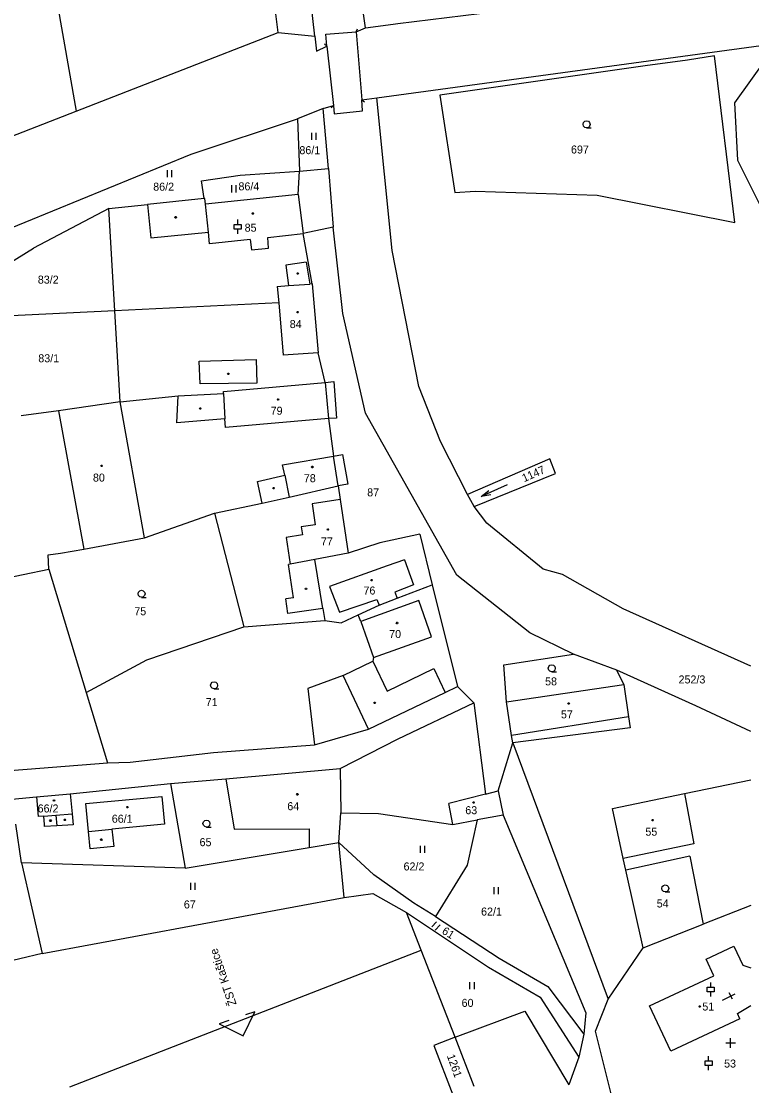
# Model space of a CAD drawing. Extents: x -812394 to -807601, y -1013097 to -1009266.
# Drawn here: x -809780.5 to -809625.5, y -1011039 to -1010813 of the extents above; entities that cross this region are included whole.
import ezdxf

# ---------------------------------------------------------------- set-up
doc = ezdxf.new("R2010")
doc.units = 0
for name, color, linetype in [('Default', 7, 'Continuous'), ('KN_HRANICE', 7, 'Continuous'), ('KN_KULTURY', 7, 'Continuous'), ('KN_PARCELY', 7, 'Continuous'), ('KN_SLUCKY', 7, 'Continuous')]:
    doc.layers.add(name, color=color, linetype=linetype)

# ---------------------------------------------------------------- blocks, each defined once
blk = doc.blocks.new('4201')
at = {"layer": 'Default'}
blk.add_line((0, 0), (-0.5, -0.5), dxfattribs=at)
blk = doc.blocks.new('304')
at = {"layer": 'Default'}
blk.add_lwpolyline([(0, 0), (-0.38, 0.1), (-0.65, 0.37), (-0.75, 0.74), (-0.65, 1.11), (-0.38, 1.38), (-0.01, 1.48), (0.36, 1.38), (0.63, 1.11), (0.73, 0.73), (0.63, 0.35), (0.36, 0.08), (-0.02, -0.02), (0.98, -0.02)], dxfattribs=at)
blk = doc.blocks.new('306')
at = {"layer": 'Default'}
for p, q in [((-0.5, 1.5), (-0.5, 0)), ((0.5, 0), (0.5, 1.5))]:
    blk.add_line(p, q, dxfattribs=at)
blk = doc.blocks.new('315')
at = {"layer": 'Default'}
for p, q in [((-1, 1), (1, 1)), ((0, 0), (0, 2))]:
    blk.add_line(p, q, dxfattribs=at)
blk = doc.blocks.new('NAHRADNI_SYMBOL')
at = {"layer": 'Default'}
blk.add_lwpolyline([(0.09, 0.15), (0.18, 0), (0.09, -0.15), (-0.09, -0.15), (-0.18, 0), (-0.09, 0.15), (0.09, 0.15)], dxfattribs=at)
blk = doc.blocks.new('802')
at = {"layer": 'Default'}
blk.add_line((-3, 0), (3, 0), dxfattribs=at)
blk.add_lwpolyline([(1, 0.5), (3, 0), (1, -0.5)], dxfattribs=at)
blk = doc.blocks.new('318')
at = {"layer": 'Default'}
blk.add_line((0, 2), (0, 3), dxfattribs=at)
blk.add_lwpolyline([(0, 0), (0, 1), (-0.75, 1), (-0.75, 2), (0, 2), (0.75, 2), (0.75, 1), (0, 1)], dxfattribs=at)
blk = doc.blocks.new('402')
at = {"layer": 'Default'}
blk.add_lwpolyline([(0.09, 0.15), (0.18, 0), (0.09, -0.15), (-0.09, -0.15), (-0.18, 0), (-0.09, 0.15), (0.09, 0.15)], dxfattribs=at)
blk = doc.blocks.new('4091')
at = {"layer": 'Default'}
for p, q in [((0, 0), (0, 3)), ((0.75, 2), (-0.75, 2))]:
    blk.add_line(p, q, dxfattribs=at)

msp = doc.modelspace()

# ---------------------------------------------------------------- linework, layer by layer
at = {"layer": 'Default'}
msp.add_lwpolyline([(-809736.51, -1011025.2), (-809738.53, -1011025.87), (-809733.47, -1011028.41), (-809730.93, -1011023.35), (-809732.95, -1011024.02)], dxfattribs=at)
at = {"layer": 'KN_HRANICE'}
for p, q in [((-809776.12, -1010790.59), (-809768.91, -1010832.11)), ((-809718.25, -1010816.21), (-809720.85, -1010791.69)), ((-809707.49, -1010814.44), (-809710.32, -1010793.53)), ((-809726.02, -1010815.44), (-809727.35, -1010804.19)), ((-809700.6, -1010813.52), (-809643.49, -1010806.47)), ((-809709.48, -1010815.3), (-809707.49, -1010814.44)), ((-809707.49, -1010814.44), (-809701.59, -1010813.65)), ((-809701.59, -1010813.65), (-809700.6, -1010813.52)), ((-809768.91, -1010832.11), (-809726.02, -1010815.44)), ((-809726.02, -1010815.44), (-809718.25, -1010816.21)), ((-809718.25, -1010816.21), (-809717.84, -1010819.37)), ((-809715.88, -1010815.78), (-809709.48, -1010815.3)), ((-809715.65, -1010818.36), (-809715.88, -1010815.78)), ((-809705.08, -1010829.3), (-809609.07, -1010816.23)), ((-809717.84, -1010819.37), (-809715.65, -1010818.36)), ((-809622.36, -1010820.88), (-809629.15, -1010830.35)), ((-809708.23, -1010829.73), (-809705.08, -1010829.3)), ((-809708.1, -1010832.05), (-809708.23, -1010829.73)), ((-809701.84, -1010861.69), (-809705.08, -1010829.3)), ((-809629.15, -1010830.35), (-809628.52, -1010842.52)), ((-809795, -1010842.25), (-809768.91, -1010832.11)), ((-809716.45, -1010831.55), (-809721.87, -1010833.74)), ((-809716.45, -1010831.55), (-809714.29, -1010830.95)), ((-809715.34, -1010844.3), (-809716.45, -1010831.55)), ((-809714.29, -1010830.95), (-809714.1, -1010832.7)), ((-809714.1, -1010832.7), (-809708.1, -1010832.05)), ((-809744.44, -1010841.28), (-809721.87, -1010833.74)), ((-809721.87, -1010833.74), (-809721.48, -1010844.89)), ((-809788.59, -1010859.35), (-809744.44, -1010841.28)), ((-809628.52, -1010842.52), (-809623.05, -1010853.45)), ((-809742.28, -1010846.91), (-809734.04, -1010845.7)), ((-809734.04, -1010845.7), (-809721.48, -1010844.89)), ((-809721.76, -1010849.8), (-809721.48, -1010844.89)), ((-809721.48, -1010844.89), (-809715.34, -1010844.3)), ((-809715.34, -1010844.3), (-809714.35, -1010856.77)), ((-809741.74, -1010850.68), (-809742.28, -1010846.91)), ((-809741.74, -1010850.68), (-809753.76, -1010851.95)), ((-809741.55, -1010850.66), (-809741.74, -1010850.68)), ((-809741.42, -1010851.87), (-809741.55, -1010850.66)), ((-809721.76, -1010849.8), (-809741.42, -1010851.87)), ((-809761.95, -1010852.82), (-809777.96, -1010861.22)), ((-809761.95, -1010852.82), (-809753.76, -1010851.95)), ((-809760.65, -1010874.53), (-809761.95, -1010852.82)), ((-809714.35, -1010856.77), (-809720.67, -1010858.1)), ((-809712.26, -1010875.07), (-809714.35, -1010856.77)), ((-809718.78, -1010868.81), (-809720.67, -1010858.1)), ((-809791.19, -1010869.46), (-809777.96, -1010861.22)), ((-809696.17, -1010890.56), (-809701.84, -1010861.69)), ((-809723.78, -1010869.17), (-809719.27, -1010868.85)), ((-809718.78, -1010868.81), (-809719.27, -1010868.85)), ((-809718.78, -1010868.81), (-809717.54, -1010883.42)), ((-809726.19, -1010869.35), (-809723.78, -1010869.17)), ((-809726.19, -1010869.35), (-809725.89, -1010872.83)), ((-809725.89, -1010872.83), (-809760.65, -1010874.53)), ((-809760.65, -1010874.53), (-809789.4, -1010875.94)), ((-809759.51, -1010893.83), (-809760.65, -1010874.53)), ((-809707.45, -1010896.24), (-809712.26, -1010875.07)), ((-809716.06, -1010889.76), (-809717.54, -1010883.42)), ((-809737.62, -1010891.67), (-809716.06, -1010889.76)), ((-809737.6, -1010892.07), (-809737.62, -1010891.67)), ((-809716.06, -1010889.76), (-809714.21, -1010889.51)), ((-809714.21, -1010889.51), (-809713.65, -1010897.28)), ((-809691.58, -1010902.27), (-809696.17, -1010890.56)), ((-809759.51, -1010893.83), (-809772.62, -1010895.72)), ((-809759.51, -1010893.83), (-809747.26, -1010892.56)), ((-809754.39, -1010922.74), (-809759.51, -1010893.83)), ((-809747.26, -1010892.56), (-809737.6, -1010892.07)), ((-809772.62, -1010895.72), (-809780.58, -1010896.79)), ((-809772.62, -1010895.72), (-809767.28, -1010925.14)), ((-809713.65, -1010897.28), (-809715.33, -1010897.38)), ((-809715.33, -1010897.38), (-809714.24, -1010905.37)), ((-809688.11, -1010930.67), (-809707.45, -1010896.24)), ((-809685.82, -1010913.52), (-809691.58, -1010902.27)), ((-809714.24, -1010905.37), (-809712.36, -1010905.04)), ((-809712.36, -1010905.04), (-809711.25, -1010911.34)), ((-809725.07, -1010907.24), (-809714.24, -1010905.37)), ((-809724.57, -1010909.43), (-809725.07, -1010907.24)), ((-809730.42, -1010910.76), (-809724.57, -1010909.43)), ((-809729.38, -1010915.34), (-809730.42, -1010910.76)), ((-809723.69, -1010914.05), (-809713.3, -1010911.69)), ((-809711.25, -1010911.34), (-809713.3, -1010911.69)), ((-809713.3, -1010911.69), (-809712.87, -1010914.61)), ((-809729.38, -1010915.34), (-809723.69, -1010914.05)), ((-809684.42, -1010916.06), (-809685.82, -1010913.52)), ((-809739.53, -1010917.47), (-809729.38, -1010915.34)), ((-809712.87, -1010914.61), (-809711.14, -1010925.98)), ((-809681.71, -1010919.57), (-809684.42, -1010916.06)), ((-809754.39, -1010922.74), (-809739.53, -1010917.47)), ((-809739.53, -1010917.47), (-809733.26, -1010941.62)), ((-809669.73, -1010929.35), (-809681.71, -1010919.57)), ((-809767.28, -1010925.14), (-809754.39, -1010922.74)), ((-809695.97, -1010921.93), (-809704.43, -1010923.75)), ((-809695.97, -1010921.93), (-809693.3, -1010932.7)), ((-809772.22, -1010925.97), (-809767.28, -1010925.14)), ((-809704.43, -1010923.75), (-809711.14, -1010925.98)), ((-809774.81, -1010926.31), (-809772.22, -1010925.97)), ((-809774.68, -1010929.4), (-809774.81, -1010926.31)), ((-809711.14, -1010925.98), (-809718.2, -1010927.32)), ((-809716.52, -1010937.73), (-809718.2, -1010927.32)), ((-809810.23, -1010936.6), (-809774.68, -1010929.4)), ((-809774.68, -1010929.4), (-809766.75, -1010955.54)), ((-809665.64, -1010930.47), (-809669.73, -1010929.35)), ((-809672.58, -1010942.91), (-809688.11, -1010930.67)), ((-809652.76, -1010937.76), (-809665.64, -1010930.47)), ((-809700.73, -1010935.54), (-809693.3, -1010932.7)), ((-809693.3, -1010932.7), (-809687.95, -1010954.31)), ((-809704.57, -1010937), (-809700.73, -1010935.54)), ((-809716.52, -1010937.73), (-809716.12, -1010940.23)), ((-809712.62, -1010940.73), (-809708.99, -1010939.05)), ((-809708.99, -1010939.05), (-809704.57, -1010937)), ((-809708.43, -1010940.5), (-809708.99, -1010939.05)), ((-809625.71, -1010949.98), (-809652.76, -1010937.76)), ((-809733.26, -1010941.62), (-809716.12, -1010940.23)), ((-809716.12, -1010940.23), (-809712.62, -1010940.73)), ((-809708.43, -1010940.5), (-809705.79, -1010948.11)), ((-809753.89, -1010948.61), (-809733.26, -1010941.62)), ((-809663.31, -1010947.39), (-809672.58, -1010942.91)), ((-809705.79, -1010948.11), (-809705.9, -1010948.93)), ((-809678.08, -1010949.7), (-809663.31, -1010947.39)), ((-809654.15, -1010950.78), (-809663.31, -1010947.39)), ((-809766.75, -1010955.54), (-809753.89, -1010948.61)), ((-809712.21, -1010951.96), (-809705.9, -1010948.93)), ((-809677.51, -1010957.55), (-809678.08, -1010949.7)), ((-809712.21, -1010951.96), (-809719.69, -1010954.69)), ((-809637.34, -1010958.4), (-809654.15, -1010950.78)), ((-809652.62, -1010953.83), (-809654.15, -1010950.78)), ((-809719.69, -1010954.69), (-809718.32, -1010966.65)), ((-809690.53, -1010955.54), (-809687.95, -1010954.31)), ((-809687.95, -1010954.31), (-809684.45, -1010957.75)), ((-809677.51, -1010957.55), (-809652.62, -1010953.83)), ((-809652.62, -1010953.83), (-809651.63, -1010960.74)), ((-809766.75, -1010955.54), (-809762.22, -1010970.5)), ((-809706.83, -1010963.33), (-809690.53, -1010955.54)), ((-809700.5, -1010965.4), (-809684.45, -1010957.75)), ((-809684.45, -1010957.75), (-809682.01, -1010977.11)), ((-809676.47, -1010964.65), (-809677.51, -1010957.55)), ((-809625.71, -1010963.85), (-809637.34, -1010958.4)), ((-809651.63, -1010960.74), (-809651.3, -1010963.06)), ((-809718.32, -1010966.65), (-809706.83, -1010963.33)), ((-809651.3, -1010963.06), (-809676.23, -1010966.23)), ((-809712.82, -1010971.72), (-809700.5, -1010965.4)), ((-809679.34, -1010976.42), (-809676.23, -1010966.23)), ((-809676.23, -1010966.23), (-809676.47, -1010964.65)), ((-809676.23, -1010966.23), (-809655.96, -1011020.63)), ((-809757.42, -1010970.37), (-809739.76, -1010968.28)), ((-809739.76, -1010968.28), (-809718.32, -1010966.65)), ((-809785.75, -1010972.3), (-809762.22, -1010970.5)), ((-809762.22, -1010970.5), (-809757.42, -1010970.37)), ((-809737.1, -1010973.85), (-809712.82, -1010971.72)), ((-809712.82, -1010971.72), (-809712.69, -1010981.07)), ((-809770.14, -1010977.1), (-809748.85, -1010974.88)), ((-809748.85, -1010974.88), (-809737.1, -1010973.85)), ((-809748.85, -1010974.88), (-809745.78, -1010992.82)), ((-809737.1, -1010973.85), (-809735.37, -1010984.59)), ((-809639.78, -1010977.02), (-809625.71, -1010974.08)), ((-809777.31, -1010977.72), (-809770.14, -1010977.1)), ((-809770.14, -1010977.1), (-809769.76, -1010981.28)), ((-809682.01, -1010977.11), (-809679.34, -1010976.42)), ((-809679.34, -1010976.42), (-809678.26, -1010981.58)), ((-809655.06, -1010980.16), (-809639.78, -1010977.02)), ((-809782.57, -1010978.23), (-809777.31, -1010977.72)), ((-809777.31, -1010977.72), (-809776.92, -1010981.88)), ((-809775.78, -1010981.78), (-809776.92, -1010981.88)), ((-809775.61, -1010983.58), (-809775.78, -1010981.78)), ((-809769.76, -1010981.28), (-809769.54, -1010983.67)), ((-809713.13, -1010987.41), (-809712.69, -1010981.07)), ((-809712.69, -1010981.07), (-809704.69, -1010981.22)), ((-809704.69, -1010981.22), (-809688.94, -1010983.58)), ((-809678.26, -1010981.58), (-809683.77, -1010982.61)), ((-809678.26, -1010981.58), (-809660.72, -1011023.58)), ((-809652.76, -1010990.81), (-809655.06, -1010980.16)), ((-809780.48, -1010991.7), (-809781.71, -1010983.51)), ((-809775.59, -1010983.98), (-809775.61, -1010983.58)), ((-809772.99, -1010983.85), (-809775.59, -1010983.98)), ((-809769.54, -1010983.67), (-809772.99, -1010983.85)), ((-809688.94, -1010983.58), (-809683.77, -1010982.61)), ((-809683.77, -1010982.61), (-809685.91, -1010992.23)), ((-809735.37, -1010984.59), (-809719.45, -1010984.53)), ((-809719.45, -1010984.53), (-809719.41, -1010988.45)), ((-809745.78, -1010992.82), (-809719.41, -1010988.45)), ((-809719.41, -1010988.45), (-809713.13, -1010987.41)), ((-809712.03, -1010999.08), (-809713.13, -1010987.41)), ((-809705.68, -1010994.29), (-809713.13, -1010987.41)), ((-809652.21, -1010993.26), (-809652.76, -1010990.81)), ((-809638.59, -1010990.28), (-809652.21, -1010993.26)), ((-809638.59, -1010990.28), (-809635.78, -1011004.74)), ((-809780.48, -1010991.7), (-809776.12, -1011010.98)), ((-809745.78, -1010992.82), (-809780.48, -1010991.7)), ((-809685.91, -1010992.23), (-809692.6, -1011003.11)), ((-809648.52, -1011009.77), (-809652.21, -1010993.26)), ((-809697.2, -1011000.25), (-809705.68, -1010994.29)), ((-809776.12, -1011010.98), (-809712.03, -1010999.08)), ((-809712.03, -1010999.08), (-809705.9, -1010998.23)), ((-809705.9, -1010998.23), (-809698.74, -1011002.28)), ((-809695.65, -1011010.24), (-809698.74, -1011002.28)), ((-809698.74, -1011002.28), (-809681.36, -1011013.87)), ((-809692.6, -1011003.11), (-809697.2, -1011000.25)), ((-809625.71, -1011000.77), (-809635.78, -1011004.74)), ((-809692.6, -1011003.11), (-809679.1, -1011011.97)), ((-809648.52, -1011009.77), (-809635.78, -1011004.74)), ((-809776.12, -1011010.98), (-809797.21, -1011015.92)), ((-809770.25, -1011039.27), (-809695.65, -1011010.24)), ((-809688.47, -1011028.73), (-809695.65, -1011010.24)), ((-809655.96, -1011020.63), (-809648.52, -1011009.77)), ((-809635.16, -1011012.17), (-809629.28, -1011009.42)), ((-809629.28, -1011009.42), (-809627.41, -1011013.42)), ((-809679.1, -1011011.97), (-809668.78, -1011017.98)), ((-809633.51, -1011015.71), (-809635.16, -1011012.17)), ((-809627.41, -1011013.42), (-809625.71, -1011014)), ((-809681.36, -1011013.87), (-809670.36, -1011020.23)), ((-809647.18, -1011022.1), (-809633.51, -1011015.71)), ((-809668.78, -1011017.98), (-809661.16, -1011028.1)), ((-809670.36, -1011020.23), (-809662.17, -1011032.99)), ((-809658.63, -1011027.44), (-809655.96, -1011020.63)), ((-809642.69, -1011031.69), (-809647.18, -1011022.1)), ((-809628.49, -1011023.72), (-809625.71, -1011022)), ((-809688.47, -1011028.73), (-809673.64, -1011023.19)), ((-809673.64, -1011023.19), (-809664.28, -1011038.85)), ((-809660.72, -1011023.58), (-809661.16, -1011028.1)), ((-809627.98, -1011024.81), (-809642.69, -1011031.69)), ((-809627.98, -1011024.81), (-809628.49, -1011023.72)), ((-809688.47, -1011028.73), (-809692.99, -1011030.49)), ((-809684.4, -1011039.22), (-809688.47, -1011028.73)), ((-809661.16, -1011028.1), (-809662.17, -1011032.99)), ((-809652.22, -1011053.19), (-809658.63, -1011027.44)), ((-809692.99, -1011030.49), (-809688.92, -1011040.98)), ((-809662.17, -1011032.99), (-809664.28, -1011038.85))]:
    msp.add_line(p, q, dxfattribs=at)
msp.add_lwpolyline([(-809691.7, -1010828.74), (-809688.53, -1010849.4), (-809684.21, -1010849.11), (-809658.29, -1010849.93), (-809629.1, -1010855.77), (-809633.37, -1010820.41), (-809639.13, -1010821.28), (-809648.14, -1010822.51)], close=True, dxfattribs=at)
msp.add_lwpolyline([(-809684.42, -1010916.06), (-809667.12, -1010909.09), (-809668.31, -1010905.92), (-809685.82, -1010913.52)], dxfattribs=at)
at = {"layer": 'KN_SLUCKY'}
for p, q in [((-809709.48, -1010815.3), (-809708.23, -1010829.73)), ((-809715.65, -1010818.36), (-809714.29, -1010830.95)), ((-809721.76, -1010849.8), (-809720.67, -1010858.1)), ((-809753.76, -1010851.95), (-809753.04, -1010859)), ((-809740.79, -1010857.85), (-809741.42, -1010851.87)), ((-809753.04, -1010859), (-809740.79, -1010857.85)), ((-809740.55, -1010860.29), (-809740.79, -1010857.85)), ((-809731.95, -1010859.34), (-809740.55, -1010860.29)), ((-809731.95, -1010859.34), (-809731.7, -1010861.58)), ((-809728.23, -1010858.97), (-809720.67, -1010858.1)), ((-809728.04, -1010861.21), (-809728.23, -1010858.97)), ((-809731.7, -1010861.58), (-809728.04, -1010861.21)), ((-809720.09, -1010864.16), (-809724.37, -1010864.8)), ((-809720.09, -1010864.16), (-809719.27, -1010868.85)), ((-809724.37, -1010864.8), (-809723.78, -1010869.17)), ((-809725.89, -1010872.83), (-809724.95, -1010883.96)), ((-809742.8, -1010885.24), (-809730.68, -1010884.82)), ((-809730.68, -1010884.82), (-809730.54, -1010889.91)), ((-809717.54, -1010883.42), (-809724.95, -1010883.96)), ((-809742.56, -1010890.05), (-809742.8, -1010885.24)), ((-809730.54, -1010889.91), (-809742.56, -1010890.05)), ((-809716.06, -1010889.76), (-809715.33, -1010897.38)), ((-809747.53, -1010898.29), (-809747.26, -1010892.56)), ((-809737.6, -1010892.07), (-809737.3, -1010897.44)), ((-809737.3, -1010897.44), (-809747.53, -1010898.29)), ((-809737.2, -1010899.28), (-809737.3, -1010897.44)), ((-809715.33, -1010897.38), (-809737.2, -1010899.28)), ((-809713.3, -1010911.69), (-809714.24, -1010905.37)), ((-809724.57, -1010909.43), (-809723.69, -1010914.05)), ((-809712.87, -1010914.61), (-809718.8, -1010915.51)), ((-809718.8, -1010915.51), (-809718.12, -1010919.96)), ((-809718.12, -1010919.96), (-809721.09, -1010920.41)), ((-809721.09, -1010920.41), (-809720.83, -1010922.09)), ((-809720.83, -1010922.09), (-809724.3, -1010922.62)), ((-809724.3, -1010922.62), (-809723.43, -1010928.32)), ((-809718.2, -1010927.32), (-809723.43, -1010928.32)), ((-809699.21, -1010927.36), (-809702.88, -1010928.67)), ((-809699.21, -1010927.36), (-809697.31, -1010932.7)), ((-809723.43, -1010928.32), (-809723.82, -1010928.4)), ((-809722.74, -1010935.45), (-809723.82, -1010928.4)), ((-809702.88, -1010928.67), (-809715.13, -1010933.03)), ((-809715.13, -1010933.03), (-809713, -1010938.48)), ((-809697.31, -1010932.7), (-809701.21, -1010934.27)), ((-809701.21, -1010934.27), (-809700.73, -1010935.54)), ((-809722.74, -1010935.45), (-809724.36, -1010935.68)), ((-809723.94, -1010938.79), (-809724.36, -1010935.68)), ((-809713, -1010938.48), (-809705.03, -1010935.8)), ((-809696.16, -1010936.04), (-809708.43, -1010940.5)), ((-809705.03, -1010935.8), (-809704.57, -1010937)), ((-809693.48, -1010943.7), (-809696.16, -1010936.04)), ((-809716.52, -1010937.73), (-809723.94, -1010938.79)), ((-809705.79, -1010948.11), (-809693.48, -1010943.7)), ((-809705.9, -1010948.93), (-809702.87, -1010955.24)), ((-809706.83, -1010963.33), (-809712.21, -1010951.96)), ((-809702.87, -1010955.24), (-809692.96, -1010950.48)), ((-809692.96, -1010950.48), (-809690.53, -1010955.54)), ((-809651.63, -1010960.74), (-809676.47, -1010964.65)), ((-809682.01, -1010977.11), (-809689.78, -1010979.12)), ((-809639.78, -1010977.02), (-809637.75, -1010987.67)), ((-809766.85, -1010979.12), (-809750.67, -1010977.62)), ((-809766.28, -1010985.05), (-809766.85, -1010979.12)), ((-809750.67, -1010977.62), (-809750.11, -1010983.48)), ((-809688.94, -1010983.58), (-809689.78, -1010979.12)), ((-809775.78, -1010981.78), (-809773.19, -1010981.57)), ((-809773.19, -1010981.57), (-809769.76, -1010981.28)), ((-809773.19, -1010981.57), (-809772.99, -1010983.85)), ((-809750.11, -1010983.48), (-809761.28, -1010984.55)), ((-809766.28, -1010985.05), (-809761.28, -1010984.55)), ((-809765.93, -1010988.73), (-809766.28, -1010985.05)), ((-809761.28, -1010984.55), (-809760.92, -1010988.26)), ((-809760.92, -1010988.26), (-809765.93, -1010988.73)), ((-809637.75, -1010987.67), (-809652.76, -1010990.81))]:
    msp.add_line(p, q, dxfattribs=at)

# ---------------------------------------------------------------- block references
at = {"layer": 'KN_KULTURY'}
for name, p in [('304', (-809660.52, -1010835.66)), ('306', (-809718.42, -1010838.2)), ('306', (-809749.07, -1010846.12)), ('306', (-809735.43, -1010849.36)), ('402', (-809747.77, -1010854.66)), ('318', (-809734.6, -1010858.16)), ('402', (-809731.38, -1010853.87)), ('402', (-809721.84, -1010866.6)), ('402', (-809721.89, -1010874.78)), ('402', (-809736.58, -1010887.9)), ('402', (-809726.02, -1010893.37)), ('402', (-809742.55, -1010895.24)), ('402', (-809763.5, -1010907.41)), ('402', (-809718.74, -1010907.68)), ('402', (-809726.99, -1010912.19)), ('402', (-809715.45, -1010920.92)), ('402', (-809706.19, -1010931.69)), ('304', (-809754.99, -1010935.33)), ('402', (-809720.08, -1010933.54)), ('402', (-809700.76, -1010940.79)), ('304', (-809667.93, -1010951.15)), ('304', (-809739.6, -1010954.76)), ('402', (-809705.51, -1010957.74)), ('402', (-809664.34, -1010957.87)), ('NAHRADNI_SYMBOL', (-809721.91, -1010977.18)), ('402', (-809773.58, -1010978.48)), ('402', (-809757.99, -1010979.91)), ('402', (-809684.53, -1010978.92)), ('402', (-809774.33, -1010982.77)), ('402', (-809771.29, -1010982.58)), ('304', (-809741.22, -1010984.12)), ('402', (-809646.54, -1010982.66)), ('402', (-809763.57, -1010986.79)), ('306', (-809695.36, -1010989.6)), ('306', (-809744.14, -1010997.47)), ('306', (-809679.74, -1010998.4)), ('304', (-809643.82, -1010997.88)), ('306', (-809684.86, -1011018.57)), ('318', (-809634.18, -1011020.12)), ('402', (-809636.51, -1011022.21)), ('315', (-809629.96, -1011030.96)), ('318', (-809634.65, -1011035.76))]:
    msp.add_blockref(name, p, dxfattribs=at)
for name, p, rotation in [('802', (-809680.16, -1010912.72), -155.74054600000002), ('306', (-809693.02, -1011005.67), -42.294903), ('4091', (-809631.72, -1011020.9), -63.43704500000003)]:
    msp.add_blockref(name, p, dxfattribs=dict(at, rotation=rotation))
at = {"layer": 'KN_SLUCKY'}
for p, rotation in [((-809709.48, -1010815.3), -162.55874399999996), ((-809715.65, -1010818.36), -88.016935), ((-809708.23, -1010829.73), 99.465473)]:
    msp.add_blockref('4201', p, dxfattribs=dict(at, rotation=rotation))
msp.add_blockref('4201', (-809714.29, -1010830.95), dxfattribs=at)

# ---------------------------------------------------------------- texts
at = {"layer": 'Default'}
msp.add_text('ŽST Kaštice', height=1.75, rotation=109.0342, dxfattribs=at).set_placement((-809734.8, -1011021.75))
at = {"layer": 'KN_PARCELY'}
for s, p in [('86/1', (-809721.5, -1010841.26)), ('697', (-809663.85, -1010841.12)), ('86/2', (-809752.53, -1010849.01)), ('86/4', (-809734.43, -1010848.94)), ('85', (-809733.12, -1010857.71)), ('83/2', (-809777.02, -1010868.74)), ('84', (-809723.55, -1010878.18)), ('83/1', (-809776.92, -1010885.44)), ('79', (-809727.6, -1010896.58)), ('80', (-809765.32, -1010910.77)), ('78', (-809720.56, -1010910.9)), ('87', (-809707.11, -1010913.91)), ('77', (-809716.93, -1010924.34)), ('76', (-809707.9, -1010934.75)), ('75', (-809756.54, -1010939.15)), ('70', (-809702.45, -1010943.99)), ('58', (-809669.35, -1010954.04)), ('252/3', (-809641.02, -1010953.63)), ('71', (-809741.38, -1010958.44)), ('57', (-809665.98, -1010961.04)), ('66/2', (-809777.06, -1010981.02)), ('64', (-809724.07, -1010980.54)), ('63', (-809686.29, -1010981.39)), ('66/1', (-809761.32, -1010983.2)), ('55', (-809648.06, -1010985.95)), ('65', (-809742.69, -1010988.18)), ('62/2', (-809699.39, -1010993.33)), ('67', (-809746.03, -1011001.4)), ('54', (-809645.65, -1011001.19)), ('62/1', (-809682.94, -1011002.91)), ('60', (-809687.07, -1011022.3)), ('51', (-809635.97, -1011023.07)), ('53', (-809631.35, -1011035.18))]:
    msp.add_text(s, height=1.7, dxfattribs=at).set_placement(p)
for s, rotation, p in [('1147', 23.892, (-809673.8, -1010910.92)), ('61', 328.362, (-809691.4, -1011006.63)), ('1261', 289.745, (-809690.22, -1011032.7))]:
    msp.add_text(s, height=1.7, rotation=rotation, dxfattribs=at).set_placement(p)

doc.saveas('drawing.dxf')
